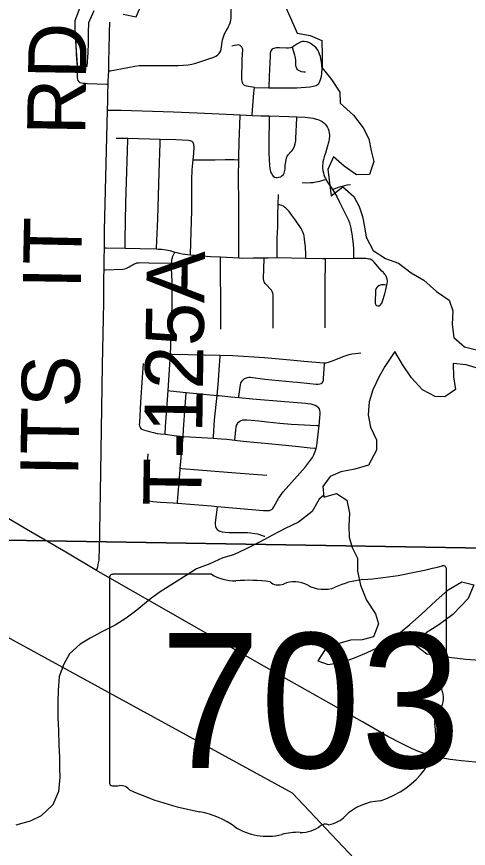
# Model space of a CAD drawing. Extents: x -38.1 to 35.9, y -2.7 to 28.5.
# Drawn here: x 22.507 to 22.949, y 16.713 to 17.526 of the extents above; entities that cross this region are included whole.
import ezdxf

# ---------------------------------------------------------------- set-up
doc = ezdxf.new("R2010")
doc.units = 0
for name, color, linetype in [('GM_X_Corporation', 7, 'Continuous'), ('GM_X_County_Road_Text', 7, 'Continuous'), ('GM_X_Interchange_Ramps', 7, 'Continuous'), ('GM_X_Interstate_Shield', 7, 'Continuous'), ('GM_X_Major_River_Text', 7, 'Continuous'), ('GM_X_Minor_Lake', 7, 'Continuous'), ('GM_X_Section', 7, 'Continuous'), ('GM_X_Section_Text', 7, 'Continuous'), ('GM_X_US_Route', 7, 'Continuous')]:
    doc.layers.add(name, color=color, linetype=linetype)

msp = doc.modelspace()

# ---------------------------------------------------------------- linework, layer by layer
at = {"layer": 'GM_X_Corporation'}
msp.add_lwpolyline([(25.41006, 13.48728), (25.08471, 13.91863), (24.54784, 14.54118), (23.96222, 15.2897), (23.39453, 15.99766), (22.84289, 16.6968), (22.77708, 16.76644), (22.2793, 17.03866), (22.17399, 17.09495), (22.11833, 17.13479), (22.08061, 17.17978), (21.96357, 17.40412), (21.78414, 17.77486), (21.74398, 17.85374), (21.71548, 17.92874), (21.69781, 17.9866), (21.69212, 18.04126), (21.69562, 18.14677), (21.71626, 18.79338), (21.76021, 19.73028), (21.76022, 19.73076)], dxfattribs=at)
at = {"layer": 'GM_X_Interchange_Ramps'}
msp.add_lwpolyline([(22.96297, 16.79619), (22.94258, 16.7981), (22.93152, 16.79947), (22.92238, 16.80104), (22.91454, 16.80279), (22.90685, 16.80502), (22.90045, 16.80726), (22.89361, 16.8101), (22.8836, 16.81498), (22.87049, 16.82202), (22.84565, 16.83616), (22.76127, 16.88395), (22.62358, 16.96233), (22.58553, 16.98435), (22.55552, 17.00227), (22.5189, 17.02338), (22.48505, 17.04305)], dxfattribs=at)
at = {"layer": 'GM_X_Interstate_Shield'}
for points in [[(22.61143, 17.52798), (22.62427, 17.52534), (22.6304, 17.53997)], [(22.56868, 17.53375), (22.56415, 17.52173), (22.56423, 17.51186), (22.56506, 17.50122), (22.56543, 17.4883), (22.56662, 17.47688), (22.57612, 17.47737), (22.57727, 17.49024), (22.57756, 17.5001), (22.57747, 17.50997), (22.57776, 17.51983), (22.58305, 17.53182)], [(22.77042, 17.53522), (22.77611, 17.52215), (22.78182, 17.50947), (22.79428, 17.50721), (22.80591, 17.50233), (22.80624, 17.48752), (22.80627, 17.47576), (22.81542, 17.46411), (22.82341, 17.45174), (22.82385, 17.4411), (22.8368, 17.42934), (22.84631, 17.41693), (22.85169, 17.40615), (22.85399, 17.39432), (22.85673, 17.38399)], [(22.85673, 17.38399), (22.85249, 17.37125), (22.83957, 17.37116), (22.8276, 17.3794), (22.81717, 17.38874), (22.81157, 17.37634), (22.81479, 17.35045), (22.82639, 17.35931), (22.8372, 17.34995), (22.84229, 17.33997), (22.8455, 17.3304), (22.84755, 17.32011), (22.84923, 17.3102), (22.85615, 17.29714), (22.86813, 17.28928), (22.88095, 17.28481), (22.89327, 17.27505), (22.90565, 17.26794), (22.91794, 17.25703), (22.93029, 17.2484), (22.93386, 17.23807), (22.93318, 17.2248), (22.93479, 17.21186), (22.94523, 17.20289), (22.95958, 17.19915)], [(22.95994, 17.1813), (22.94711, 17.18538), (22.93422, 17.18643), (22.93469, 17.17351), (22.9367, 17.16132), (22.92628, 17.15396), (22.91678, 17.15417), (22.9044, 17.1609), (22.89364, 17.17253), (22.88481, 17.18563), (22.87712, 17.19834), (22.8673, 17.18375), (22.86176, 17.174), (22.85576, 17.16085), (22.85208, 17.14916), (22.85104, 17.13627), (22.85343, 17.12445), (22.85923, 17.11179), (22.85938, 17.10192), (22.85146, 17.08728), (22.83807, 17.08341), (22.82434, 17.08067), (22.81397, 17.07597), (22.80692, 17.06625), (22.80783, 17.05598), (22.82006, 17.05951), (22.83017, 17.05283), (22.83293, 17.04024), (22.83227, 17.02772), (22.8324, 17.01671)], [(22.8324, 17.01671), (22.8356, 17.00677), (22.84069, 16.9964), (22.84078, 16.98349), (22.84351, 16.96976), (22.84964, 16.9552), (22.85846, 16.94172), (22.86129, 16.93216), (22.85644, 16.91936), (22.84536, 16.91657), (22.83395, 16.91606), (22.82133, 16.91255), (22.80906, 16.90713), (22.80197, 16.89589), (22.81214, 16.89225), (22.82625, 16.89459), (22.83928, 16.89962), (22.85001, 16.90394), (22.86, 16.90865), (22.87233, 16.91635), (22.88237, 16.92372), (22.89204, 16.93147), (22.90329, 16.94148), (22.91725, 16.95445), (22.92927, 16.96519), (22.94275, 16.97324), (22.95446, 16.97032), (22.94884, 16.95678), (22.93405, 16.94117), (22.92015, 16.93123), (22.90781, 16.92315), (22.8958, 16.91241), (22.9085, 16.90263), (22.92175, 16.90082), (22.93311, 16.89904), (22.94676, 16.8976), (22.96041, 16.89653)]]:
    msp.add_lwpolyline(points, dxfattribs=at)
at = {"layer": 'GM_X_Major_River_Text'}
for p, q in [((22.70677, 17.29079), (22.72449, 17.28983)), ((22.76208, 17.29007), (22.7902, 17.2895)), ((22.80937, 17.2892), (22.83697, 17.28959))]:
    msp.add_line(p, q, dxfattribs=at)
for points in [[(22.59731, 17.47256), (22.59884, 17.47283), (22.61608, 17.47591), (22.62284, 17.47715), (22.62722, 17.47775), (22.62992, 17.47797), (22.63408, 17.47797), (22.64409, 17.47794), (22.66517, 17.47796), (22.67021, 17.47822), (22.67495, 17.4786), (22.67852, 17.47917), (22.68271, 17.48014), (22.70024, 17.48615), (22.70224, 17.48715), (22.70384, 17.48808), (22.70515, 17.48927), (22.7061, 17.4906), (22.70697, 17.49234), (22.70735, 17.49372), (22.70863, 17.50295), (22.70952, 17.50605), (22.71069, 17.50901), (22.7122, 17.51172), (22.71376, 17.51449), (22.71461, 17.5161), (22.71564, 17.51788), (22.71651, 17.52022), (22.71688, 17.52248), (22.71699, 17.52391), (22.71718, 17.53376)], [(22.59682, 17.45933), (22.5956, 17.45938), (22.57666, 17.46006), (22.57432, 17.46015), (22.57246, 17.46031), (22.57068, 17.46053), (22.56944, 17.46104), (22.56833, 17.46178), (22.5674, 17.46309), (22.56703, 17.46462), (22.56689, 17.46613), (22.56678, 17.4735), (22.56677, 17.47812), (22.56639, 17.48392), (22.56611, 17.48753), (22.56539, 17.4962), (22.5648, 17.50833), (22.56449, 17.51483)], [(22.59731, 17.47256), (22.59755, 17.4825), (22.59779, 17.49278), (22.59809, 17.50996), (22.59827, 17.52012)], [(22.7401, 17.45644), (22.75409, 17.45614), (22.76612, 17.45613), (22.78142, 17.45591), (22.7944, 17.45718), (22.79728, 17.45769), (22.80042, 17.45851), (22.80164, 17.45922), (22.80285, 17.46038), (22.80365, 17.46173), (22.80425, 17.46318), (22.80492, 17.46518), (22.80545, 17.46728), (22.80586, 17.47049), (22.806, 17.47466), (22.80568, 17.47827), (22.80535, 17.48155), (22.80485, 17.48434), (22.80437, 17.48664), (22.80363, 17.48905), (22.80287, 17.4909), (22.80198, 17.49284), (22.80015, 17.49516), (22.79825, 17.49696), (22.79581, 17.49876), (22.79372, 17.49993), (22.79105, 17.50102), (22.78867, 17.50137), (22.78689, 17.50121), (22.7855, 17.5009), (22.7842, 17.50036), (22.78134, 17.4988), (22.77954, 17.49746), (22.7778, 17.49632), (22.77709, 17.49595), (22.77625, 17.4955), (22.77502, 17.49514), (22.77312, 17.49493), (22.77132, 17.49478), (22.76444, 17.49503), (22.76145, 17.49503), (22.75997, 17.49487), (22.75884, 17.49462), (22.75781, 17.49415), (22.75694, 17.49357), (22.75612, 17.4925), (22.75573, 17.49143), (22.7554, 17.49004), (22.75525, 17.4884), (22.75514, 17.48716), (22.75426, 17.46737), (22.75409, 17.45614)], [(22.7401, 17.45644), (22.73196, 17.45778), (22.73056, 17.45823), (22.72971, 17.45883), (22.72901, 17.45953), (22.72852, 17.46038), (22.72816, 17.46128), (22.72786, 17.46247), (22.72771, 17.46388), (22.72804, 17.48377), (22.72846, 17.49351), (22.72824, 17.49465), (22.72766, 17.49576), (22.72684, 17.49664), (22.72586, 17.49742), (22.72499, 17.49784), (22.72394, 17.49804), (22.72264, 17.49794), (22.72054, 17.49759), (22.71768, 17.4968)], [(22.78994, 17.47146), (22.78809, 17.47151), (22.78608, 17.47177), (22.78454, 17.47233), (22.78308, 17.47305), (22.78213, 17.47387), (22.7814, 17.47481), (22.78074, 17.47644), (22.78042, 17.47838), (22.78033, 17.48152), (22.78028, 17.48312), (22.78006, 17.48508), (22.7798, 17.48659), (22.77939, 17.48813), (22.77826, 17.49211), (22.77709, 17.49595)], [(22.59682, 17.45933), (22.59692, 17.4627), (22.59713, 17.46787), (22.59731, 17.47256)], [(22.59612, 17.43415), (22.59616, 17.43575), (22.59632, 17.44164), (22.59658, 17.45085), (22.59682, 17.45933)], [(22.73771, 17.42916), (22.73778, 17.43011), (22.73899, 17.4471), (22.73936, 17.45105), (22.7401, 17.45644)], [(22.59311, 17.29975), (22.59336, 17.3165), (22.59612, 17.43415)], [(22.59612, 17.43415), (22.59769, 17.43414), (22.6096, 17.4341), (22.66078, 17.43265), (22.6837, 17.43157), (22.70551, 17.43067), (22.72594, 17.42971), (22.73771, 17.42916), (22.74622, 17.42876), (22.75424, 17.42858), (22.77338, 17.42812), (22.78132, 17.4278), (22.78945, 17.42748), (22.79214, 17.42723), (22.79475, 17.42682), (22.79728, 17.42636), (22.80041, 17.42559), (22.80205, 17.42508), (22.80349, 17.42452), (22.80488, 17.42385), (22.80621, 17.4231), (22.80766, 17.42195), (22.80899, 17.42052), (22.81023, 17.41893), (22.81131, 17.41734), (22.81203, 17.41584), (22.81265, 17.41415), (22.81311, 17.41215), (22.81332, 17.40989), (22.81337, 17.40829), (22.81315, 17.40639), (22.81291, 17.40511), (22.81269, 17.40388), (22.80937, 17.39224), (22.80877, 17.39046), (22.80814, 17.38858), (22.80779, 17.38734), (22.80742, 17.38598), (22.80693, 17.3836), (22.80672, 17.38187), (22.8066, 17.38043), (22.80656, 17.37772), (22.80681, 17.37513), (22.8073, 17.37299), (22.80784, 17.37098), (22.80858, 17.36904), (22.80924, 17.36765), (22.8099, 17.36636), (22.8108, 17.36477), (22.81198, 17.36302), (22.81631, 17.35653), (22.81869, 17.35296), (22.82071, 17.34915), (22.82322, 17.34434), (22.82677, 17.33718), (22.83076, 17.32926), (22.83199, 17.32655), (22.83282, 17.324), (22.83348, 17.32158), (22.83414, 17.31899), (22.83466, 17.31658), (22.83513, 17.31348), (22.83596, 17.30806), (22.83653, 17.3032), (22.83676, 17.29826), (22.83695, 17.29038), (22.83697, 17.28959)], [(22.72449, 17.28983), (22.72456, 17.30812), (22.72464, 17.33016), (22.72458, 17.34254), (22.72442, 17.36948), (22.72466, 17.38582), (22.7247, 17.38826), (22.72508, 17.40352), (22.72523, 17.41128), (22.72591, 17.42906), (22.72594, 17.42971)], [(22.75424, 17.42858), (22.75423, 17.4275), (22.75418, 17.42164), (22.75412, 17.40758), (22.75402, 17.39209), (22.75415, 17.38622), (22.75466, 17.37969), (22.75497, 17.37726), (22.75556, 17.37421), (22.75594, 17.37326), (22.75642, 17.37226), (22.75738, 17.37086), (22.7583, 17.36984), (22.75965, 17.36888), (22.76105, 17.36855), (22.76196, 17.36852), (22.76355, 17.36865), (22.76524, 17.36913), (22.76625, 17.36961), (22.76716, 17.37024), (22.76818, 17.37135), (22.7689, 17.3725), (22.76943, 17.37395), (22.76971, 17.37534), (22.76985, 17.3767), (22.77, 17.37833), (22.7701, 17.38012), (22.77033, 17.38199), (22.77086, 17.38566), (22.77138, 17.38749), (22.77201, 17.38922), (22.77288, 17.39057), (22.77404, 17.39178), (22.77529, 17.39313), (22.77683, 17.39472), (22.77779, 17.39602), (22.77851, 17.39736), (22.77923, 17.3992), (22.77981, 17.40142), (22.78029, 17.40416), (22.78052, 17.40652), (22.78128, 17.42676), (22.78132, 17.4278)], [(22.60477, 17.40702), (22.61363, 17.4068), (22.61594, 17.40675), (22.64782, 17.40595), (22.6631, 17.40557), (22.67543, 17.40485), (22.67656, 17.40463), (22.6778, 17.40422), (22.67913, 17.40353)], [(22.61328, 17.29933), (22.61329, 17.30023), (22.61336, 17.30774), (22.61418, 17.34365), (22.6159, 17.40539), (22.61594, 17.40675)], [(22.64419, 17.29852), (22.64422, 17.29935), (22.64541, 17.32801), (22.64677, 17.37331), (22.64769, 17.40186), (22.64782, 17.40595)], [(22.67728, 17.29273), (22.67774, 17.30486), (22.67859, 17.33589), (22.67879, 17.36658), (22.67879, 17.36928), (22.67895, 17.37249), (22.6791, 17.37587), (22.67943, 17.37932), (22.68, 17.38576), (22.68054, 17.3919), (22.6807, 17.39407), (22.68082, 17.39632), (22.68078, 17.39843), (22.68063, 17.40053), (22.68033, 17.4018), (22.67987, 17.40262), (22.67913, 17.40353)], [(22.68, 17.38576), (22.68196, 17.38581), (22.69015, 17.3858), (22.70137, 17.38561), (22.71125, 17.38595), (22.71991, 17.38591), (22.7237, 17.38584), (22.72466, 17.38582)], [(22.78659, 17.36341), (22.79086, 17.36333), (22.79479, 17.36339), (22.79727, 17.36363), (22.79994, 17.36411), (22.80395, 17.36497), (22.8082, 17.36598), (22.8099, 17.36636)], [(22.81631, 17.35653), (22.81714, 17.35689), (22.81936, 17.35786), (22.82066, 17.3584), (22.82205, 17.35886), (22.82448, 17.35964), (22.8282, 17.36065), (22.83067, 17.36113), (22.8338, 17.36152)], [(22.76208, 17.29007), (22.76205, 17.30422), (22.76222, 17.30925), (22.76245, 17.31423), (22.76268, 17.32028), (22.76283, 17.32547), (22.76291, 17.33201), (22.76314, 17.34188), (22.76337, 17.35188)], [(22.7902, 17.2895), (22.79002, 17.29524), (22.78988, 17.29868), (22.78971, 17.30098), (22.78925, 17.30532), (22.78894, 17.30821), (22.78846, 17.31123), (22.7881, 17.31283), (22.78761, 17.31424), (22.78663, 17.31656), (22.78549, 17.31856), (22.77995, 17.32664), (22.77624, 17.33202), (22.77379, 17.33508), (22.77072, 17.33841), (22.76936, 17.33953), (22.76818, 17.34025), (22.7667, 17.34089), (22.76439, 17.34155), (22.76314, 17.34188)], [(22.5928, 17.27825), (22.59294, 17.28864), (22.59311, 17.29975)], [(22.59311, 17.29975), (22.59469, 17.29972), (22.61328, 17.29933)], [(22.61328, 17.29933), (22.62795, 17.29901), (22.64419, 17.29852)], [(22.64419, 17.29852), (22.64582, 17.29847), (22.64903, 17.29829), (22.65306, 17.2978), (22.65721, 17.29695), (22.66105, 17.29588), (22.66211, 17.29557)], [(22.65242, 17.11735), (22.65303, 17.12512), (22.65535, 17.16003), (22.65766, 17.19582), (22.65817, 17.20376), (22.65935, 17.24409), (22.65941, 17.26709), (22.65875, 17.27947), (22.65895, 17.28464), (22.65908, 17.28759), (22.65931, 17.28894), (22.65959, 17.28998), (22.65988, 17.29073), (22.66169, 17.29471), (22.66211, 17.29557)], [(22.66211, 17.29557), (22.664, 17.29501), (22.66638, 17.29435), (22.66918, 17.29378), (22.67181, 17.29345), (22.67728, 17.29273)], [(22.67728, 17.29273), (22.69692, 17.29132), (22.70677, 17.29079)], [(22.70704, 17.22), (22.70703, 17.22062), (22.70692, 17.24903), (22.70684, 17.27385), (22.70678, 17.29014), (22.70677, 17.29079)], [(22.72449, 17.28983), (22.72807, 17.28964), (22.73865, 17.28978), (22.74956, 17.28993)], [(22.75834, 17.22111), (22.75824, 17.24835), (22.75825, 17.25163), (22.75819, 17.25347), (22.75795, 17.25536), (22.75733, 17.25695), (22.75648, 17.25841), (22.75556, 17.2594), (22.75169, 17.26341), (22.75054, 17.26489), (22.74954, 17.26642), (22.74901, 17.26788), (22.74877, 17.26939), (22.74953, 17.28912), (22.74956, 17.28993)], [(22.74956, 17.28993), (22.75337, 17.28999), (22.76208, 17.29007)], [(22.7902, 17.2895), (22.80648, 17.28917), (22.80937, 17.2892)], [(22.80919, 17.22157), (22.80916, 17.23735), (22.80912, 17.26259), (22.80937, 17.28824), (22.80937, 17.2892)], [(22.83697, 17.28959), (22.84244, 17.28967), (22.84626, 17.28953), (22.8489, 17.2894), (22.85161, 17.28891)], [(22.86919, 17.26301), (22.86725, 17.26334), (22.86578, 17.26346), (22.86413, 17.26337), (22.86273, 17.26309), (22.86154, 17.26255), (22.86039, 17.26168), (22.85957, 17.26086), (22.85895, 17.26004), (22.85859, 17.25926), (22.85838, 17.2584), (22.85833, 17.25758), (22.85795, 17.24648), (22.85791, 17.24548), (22.85818, 17.24463), (22.85872, 17.24392), (22.85958, 17.24339), (22.86049, 17.24307), (22.86151, 17.24294), (22.86213, 17.24302), (22.86332, 17.24381), (22.86394, 17.24479), (22.86435, 17.24561), (22.86476, 17.24665), (22.86513, 17.24767), (22.86735, 17.25478), (22.868, 17.25725), (22.86875, 17.26007), (22.86985, 17.26473), (22.86996, 17.26605), (22.86991, 17.26749), (22.86976, 17.26888), (22.86951, 17.26995), (22.8691, 17.27107), (22.86868, 17.27197), (22.86821, 17.27272), (22.8677, 17.27343), (22.86712, 17.27418), (22.86606, 17.27541), (22.86465, 17.27698), (22.85682, 17.28606), (22.85581, 17.28692), (22.85465, 17.28768), (22.85317, 17.28842), (22.85161, 17.28891)], [(22.5928, 17.27825), (22.5939, 17.2783), (22.61129, 17.2789), (22.61308, 17.27922), (22.61464, 17.27973), (22.616, 17.28032), (22.61745, 17.28102), (22.6191, 17.2819), (22.62084, 17.28309), (22.62217, 17.28387), (22.6234, 17.28446), (22.62475, 17.28488), (22.62631, 17.28511), (22.62778, 17.28521), (22.63643, 17.2851), (22.65778, 17.28466), (22.65895, 17.28464)], [(22.58553, 16.98435), (22.5866, 16.98773), (22.58711, 16.98964), (22.58748, 16.99177), (22.58784, 16.99435), (22.58814, 16.99876), (22.58828, 17.0028), (22.58954, 17.08049), (22.59128, 17.18484), (22.59224, 17.23081), (22.59243, 17.24576), (22.59268, 17.27055), (22.5928, 17.27825)], [(22.65766, 17.19582), (22.6593, 17.19579), (22.70633, 17.19475), (22.71883, 17.19447), (22.74989, 17.19256), (22.77829, 17.1898), (22.78812, 17.18876), (22.80785, 17.18719), (22.80862, 17.18725), (22.8099, 17.18736), (22.81241, 17.18777), (22.8164, 17.18929), (22.8268, 17.19356), (22.82869, 17.1942), (22.83049, 17.19473), (22.83267, 17.19531), (22.83527, 17.19589), (22.83859, 17.19638), (22.84398, 17.19712)], [(22.69963, 17.1135), (22.69974, 17.11524), (22.70078, 17.13155), (22.70332, 17.15537), (22.70485, 17.16973), (22.70551, 17.18024), (22.70625, 17.19339), (22.70633, 17.19475)], [(22.63088, 17.18645), (22.63003, 17.17291), (22.62854, 17.14877), (22.6273, 17.12844), (22.62722, 17.12706), (22.62737, 17.12573), (22.62762, 17.12486), (22.62811, 17.12404), (22.62882, 17.12318), (22.62976, 17.1224), (22.6312, 17.12182), (22.63808, 17.11968), (22.64123, 17.119), (22.64485, 17.11826), (22.64803, 17.11785), (22.65242, 17.11735), (22.66134, 17.11628), (22.67016, 17.11537), (22.67085, 17.11531), (22.68271, 17.11454), (22.69963, 17.1135), (22.70726, 17.11302), (22.71278, 17.11246), (22.72065, 17.11155), (22.72884, 17.1106), (22.75698, 17.10789), (22.78021, 17.10581), (22.79439, 17.10428), (22.7989, 17.10379), (22.80012, 17.10358)], [(22.72453, 17.15342), (22.72463, 17.15421), (22.72583, 17.16359), (22.7261, 17.16572), (22.72669, 17.16767), (22.72749, 17.16914), (22.72844, 17.17043), (22.72975, 17.17156), (22.73126, 17.17237), (22.73303, 17.17286), (22.73451, 17.17306), (22.73605, 17.17306), (22.75002, 17.17128), (22.77737, 17.1687), (22.78203, 17.16817), (22.79422, 17.16691), (22.8003, 17.16645), (22.80227, 17.16636), (22.80402, 17.16661), (22.80502, 17.16692), (22.80602, 17.16761), (22.80684, 17.16861), (22.80734, 17.16993), (22.8076, 17.17231), (22.80852, 17.18571), (22.80862, 17.18725)], [(22.65535, 17.16003), (22.65746, 17.15982), (22.67309, 17.15831), (22.70332, 17.15537), (22.70539, 17.15516), (22.71689, 17.15411), (22.72453, 17.15342), (22.73815, 17.15217), (22.76959, 17.14928), (22.79011, 17.1477), (22.79222, 17.14747), (22.79503, 17.147), (22.79701, 17.14646), (22.79914, 17.14578), (22.80097, 17.14486), (22.8027, 17.14359)], [(22.66461, 17.0501), (22.66474, 17.05165), (22.66724, 17.0826), (22.66737, 17.08411), (22.66791, 17.09048), (22.66863, 17.09885), (22.67008, 17.1145), (22.67016, 17.11537), (22.67061, 17.12221), (22.67181, 17.14034), (22.67303, 17.15744), (22.67309, 17.15831)], [(22.63342, 17.0546), (22.63394, 17.05385), (22.63471, 17.05303), (22.63563, 17.05252), (22.63682, 17.05224), (22.64046, 17.05165), (22.64411, 17.05129), (22.64786, 17.05107), (22.66029, 17.05045), (22.66461, 17.0501), (22.69745, 17.04745), (22.70339, 17.04692), (22.73743, 17.04387), (22.74883, 17.043), (22.7512, 17.0428), (22.75305, 17.04285), (22.75449, 17.04301), (22.75593, 17.04337), (22.75716, 17.04409), (22.75798, 17.04496), (22.75886, 17.04635), (22.76202, 17.05247), (22.76373, 17.05524), (22.76491, 17.05689), (22.76634, 17.05889), (22.76806, 17.06099), (22.78997, 17.08567), (22.79662, 17.09466), (22.79729, 17.09593), (22.79795, 17.09725), (22.79877, 17.09901), (22.79954, 17.1014), (22.80012, 17.10358), (22.80082, 17.10654), (22.80135, 17.10913), (22.80173, 17.11181), (22.80314, 17.126), (22.80388, 17.13343), (22.80422, 17.13729), (22.80424, 17.13922), (22.80399, 17.14075), (22.80346, 17.14218), (22.8027, 17.14359)], [(22.72065, 17.11155), (22.72179, 17.12183), (22.72209, 17.1242), (22.72246, 17.12584), (22.72291, 17.12703), (22.72346, 17.12805), (22.72444, 17.12921), (22.72554, 17.13009), (22.72681, 17.13082), (22.72838, 17.13139), (22.7303, 17.13166), (22.73253, 17.13157), (22.73675, 17.13126), (22.74407, 17.13043), (22.75225, 17.12962), (22.76482, 17.12834), (22.77593, 17.12742), (22.78273, 17.12694), (22.80082, 17.12606), (22.80314, 17.126)], [(22.63342, 17.0546), (22.63311, 17.05643), (22.63311, 17.05828), (22.63318, 17.06059), (22.63348, 17.06469), (22.63594, 17.09831)], [(22.66737, 17.08411), (22.66883, 17.084), (22.72162, 17.07973), (22.7389, 17.0784), (22.75188, 17.07743)], [(22.70339, 17.04692), (22.70328, 17.04605), (22.70153, 17.03128), (22.70147, 17.02926), (22.70166, 17.02725), (22.70239, 17.02549), (22.70336, 17.02433), (22.70482, 17.02318), (22.70616, 17.02257), (22.70819, 17.02189), (22.71127, 17.02154), (22.71503, 17.02139), (22.73056, 17.02139), (22.73318, 17.02131), (22.7361, 17.02108), (22.74017, 17.02047), (22.74294, 17.01991), (22.74949, 17.01792), (22.75005, 17.01765)]]:
    msp.add_lwpolyline(points, dxfattribs=at)
at = {"layer": 'GM_X_Section'}
msp.add_lwpolyline([(22.80766, 17.05786), (22.80322, 17.05381), (22.79649, 17.04181), (22.78296, 17.03148), (22.76991, 17.02531), (22.7576, 17.01875), (22.74491, 17.01182), (22.73108, 17.00491), (22.71956, 16.99947), (22.70886, 16.99667), (22.69619, 16.99088), (22.68316, 16.98585), (22.67313, 16.97924), (22.66158, 16.97228), (22.6477, 16.96347), (22.63805, 16.95647), (22.62488, 16.94537), (22.61445, 16.93763), (22.60366, 16.93065), (22.59059, 16.92411), (22.57906, 16.91791), (22.56943, 16.91204), (22.55896, 16.90278), (22.55342, 16.89266), (22.54897, 16.8806), (22.5479, 16.86696), (22.54765, 16.85558), (22.54769, 16.84039), (22.54817, 16.82785), (22.5486, 16.81341), (22.54909, 16.80125), (22.54925, 16.79138), (22.54942, 16.78188), (22.54835, 16.76824), (22.54274, 16.75507), (22.5311, 16.74432), (22.52035, 16.73924), (22.50659, 16.73537)], dxfattribs=at)
at = {"layer": 'GM_X_Section_Text'}
for p, q in [((22.69792, 16.98059), (22.6014, 16.98059)), ((22.92774, 16.88086), (22.92774, 16.98555)), ((22.59815, 16.97714), (22.59815, 16.77702)), ((22.9277, 16.88089), (22.92774, 16.88086))]:
    msp.add_line(p, q, dxfattribs=at)
for centre, major_axis, start_param, end_param in [((22.81033, 17.25342), (0.34952, 0), 4.814394, 5.042369), ((22.92408, 16.98598), (0.00367, 0), 6.141152, 7.989035), ((22.60193, 16.97757), (0.00382, 0), 1.712693, 3.28349), ((22.7209, 17.00382), (0.03703, 0), 4.042523, 4.731795), ((22.73318, 16.86824), (0.13295, 0), 1.404758, 1.657858), ((22.76337, 16.97861), (0.01068, 0), 3.836095, 5.185415), ((22.77905, 16.95548), (0.02221, 0), 0.950623, 2.079405), ((22.80772, 16.9872), (0.02672, 0), 4.081561, 5.145723), ((22.85492, 16.91947), (0.07032, 0), 1.699011, 2.107814), ((22.92382, 16.88046), (0.00393, 0), 5.05454, 6.418171), ((22.92689, 16.87318), (0.00568, 0), 1.883978, 3.671073), ((22.89076, 16.85994), (0.03409, 0), 5.934695, 6.695948), ((22.94088, 16.83705), (0.0248, 0), 2.387724, 3.262537), ((22.82991, 16.82374), (0.08742, 0), 5.101752, 6.440018), ((22.60196, 16.77659), (0.00385, 0), 3.00124, 4.508301), ((22.60255, 16.79706), (0.0294, 0), 4.665946, 4.897461), ((22.60856, 16.76548), (0.0106, 0), 0.519207, 1.627899), ((22.74239, 16.94528), (0.2524, 0), 4.195997, 4.488961), ((22.86677, 16.72084), (0.04788, 0), 1.647645, 2.488434), ((22.66714, 16.68712), (0.07897, 0), 0.823519, 1.323587), ((22.80611, 16.75763), (0.02824, 0), 4.937069, 5.64225), ((22.78516, 16.7495), (0.0267, 0), 4.691044, 5.507374), ((22.80932, 16.73012), (0.00752, 0), 1.147584, 2.315152), ((22.75255, 16.76449), (0.05011, 0), 4.026481, 4.996735), ((22.7815, 16.6953), (0.04118, 0), 1.495662, 1.94098)]:
    msp.add_ellipse(centre, major_axis=major_axis, ratio=0.8, start_param=start_param, end_param=end_param, dxfattribs=at)
at = {"layer": 'GM_X_US_Route'}
for points in [[(23.0833, 18.00706), (23.08302, 17.00397), (21.98921, 17.02221), (22.01452, 18.02655)], [(21.98921, 17.02221), (23.08302, 17.00397), (23.0619, 15.99964), (21.96625, 16.01981)]]:
    msp.add_lwpolyline(points, close=True, dxfattribs=at)

# ---------------------------------------------------------------- texts
at = {"layer": 'GM_X_County_Road_Text'}
for s, p in [('s', (22.75924, 16.86378)), ('r', (22.75923, 16.86378))]:
    msp.add_text(s, height=0.000189, dxfattribs=at).set_placement(p)
msp.add_text('703', height=0.000189, rotation=0.00001, dxfattribs=at).set_placement((22.69238, 16.85))
at = {"layer": 'GM_X_Minor_Lake'}
for s, height, rotation, p in [('RD', 0.056818, 89.03633, (22.5742, 17.40946)), ('T', 0.05682, 88.75919, (22.57038, 17.28243)), ('T-125A', 0.056818, 89.13232, (22.68775, 17.04711)), ('I', 0.05682, 89.1608, (22.57004, 17.25921)), ('ITS', 0.056818, 89.08297, (22.56753, 17.07591))]:
    msp.add_text(s, height=height, rotation=rotation, dxfattribs=at).set_placement(p)
at = {"layer": 'GM_X_Section_Text'}
msp.add_text('703', height=0.131836, dxfattribs=at).set_placement((22.64762, 16.79114))

doc.saveas('drawing.dxf')
